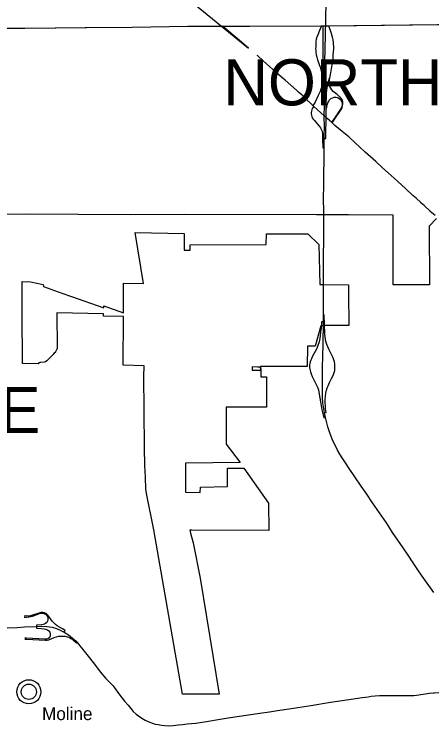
# Model space of a CAD drawing. Extents: x 0 to 851, y 0 to 440.
# Drawn here: x 378.43 to 401.2, y 321.16 to 359.94 of the extents above; entities that cross this region are included whole.
import ezdxf

# ---------------------------------------------------------------- set-up
doc = ezdxf.new("R2010")
doc.units = 0
for name, color, linetype in [('DV_X_Corp_Line', 7, 'Continuous'), ('GM_X_Corporation_Text', 7, 'Continuous'), ('GM_X_County', 7, 'Continuous'), ('GM_X_Interchange_Ramps', 7, 'Continuous'), ('GM_X_Interstate_Route', 7, 'Continuous'), ('GM_X_State_Route', 7, 'Continuous')]:
    doc.layers.add(name, color=color, linetype=linetype)

msp = doc.modelspace()

# ---------------------------------------------------------------- linework, layer by layer
at = {"layer": 'DV_X_Corp_Line'}
for points in [[(375.703, 359.197), (379.013, 359.176), (382.394, 359.212), (384.851, 359.238), (387.892, 359.281), (395.425, 359.31), (415.195, 359.534)], [(401.447, 348.807), (401.054, 348.391), (401.067, 345.188), (399.088, 345.195), (399.098, 348.986), (396.648, 348.999), (395.34, 349.005), (395.283, 349.006), (394.915, 349.002), (387.707, 349.029), (384.758, 349.005), (379.084, 349.033), (371.878, 349.031)]]:
    msp.add_lwpolyline(points, dxfattribs=at)
msp.add_lwpolyline([(378.861, 345.366), (379.32, 345.347), (380.003, 345.213), (380.023, 345.103), (381.02, 344.739), (381.547, 344.553), (383.317, 343.928), (383.315, 344.038), (384.385, 343.656), (384.388, 345.287), (385.483, 345.27), (385.027, 348.044), (387.697, 347.989), (387.7, 347.08), (388.025, 347.075), (388.019, 347.378), (392.169, 347.392), (392.176, 347.969), (394.444, 347.976), (395.035, 347.394), (395.093, 345.205), (395.254, 345.204), (395.31, 345.206), (396.661, 345.192), (396.663, 344.724), (396.666, 342.974), (395.363, 342.964), (395.311, 342.962), (395.215, 342.961), (395.183, 342.96), (395.146, 342.961), (394.841, 341.848), (394.425, 341.853), (394.405, 340.747), (393.308, 340.74), (392.197, 340.734), (391.866, 340.733), (391.867, 340.558), (391.862, 340.703), (391.69, 340.708), (391.398, 340.713), (391.398, 340.545), (391.867, 340.545), (391.868, 340.171), (392.181, 340.175), (392.187, 338.518), (389.994, 338.522), (389.994, 336.511), (390.742, 335.506), (387.76, 335.47), (387.764, 334.173), (387.767, 333.893), (388.571, 333.865), (388.58, 334.156), (390.063, 334.194), (390.062, 335.19), (390.947, 335.19), (392.297, 333.286), (392.311, 331.803), (388.108, 331.817), (387.997, 331.817), (388.037, 331.651), (388.184, 331.125), (388.559, 329.206), (389.6, 322.879), (387.61, 322.882), (386.05, 331.842), (385.642, 333.819), (385.6, 334.076), (385.581, 334.683), (385.56, 335.051), (385.556, 335.303), (385.54, 336.337), (385.501, 340.268), (385.51, 340.688), (385.516, 340.782), (384.37, 340.809), (384.384, 343.461), (383.299, 343.474), (383.295, 343.611), (380.759, 343.654), (380.772, 341.731), (380.778, 341.705), (380.76, 341.676), (380.719, 341.606), (380.68, 341.536), (380.671, 341.52), (380.614, 341.463), (380.594, 341.443), (380.546, 341.395), (380.45, 341.282), (380.39, 341.225), (380.313, 341.148), (380.204, 341.048), (380.141, 340.988), (380.064, 340.97), (379.877, 340.962), (379.823, 340.951), (379.776, 340.93), (379.743, 340.892), (378.884, 340.898), (378.868, 343.682), (378.866, 344.063)], close=True, dxfattribs=at)
for radius in [0.658, 0.417]:
    msp.add_circle((379.225, 323.008), radius, dxfattribs=at)
at = {"layer": 'GM_X_County'}
msp.add_lwpolyline([(377.893, 359.183), (379.009, 359.176), (382.288, 359.211), (384.851, 359.238), (387.892, 359.281), (388.261, 359.282), (388.38, 359.283), (388.712, 359.284), (388.751, 359.284), (389.413, 359.287), (389.783, 359.288), (390.584, 359.291), (391.285, 359.283), (395.187, 359.309), (395.259, 359.31), (395.406, 359.31), (395.583, 359.312), (400.152, 359.363), (403.796, 359.403)], dxfattribs=at)
at = {"layer": 'GM_X_Interchange_Ramps'}
for points in [[(395.259, 359.31), (395.25, 358.08), (395.238, 356.341), (395.232, 356.272), (395.22, 356.18), (395.201, 356.059), (395.179, 355.952), (395.155, 355.851), (395.104, 355.73), (395.011, 355.502), (394.846, 355.152), (394.768, 355.03), (394.705, 354.959)], [(395.187, 359.309), (395.138, 359.178), (395.078, 359.044), (394.985, 358.819), (394.931, 358.692), (394.897, 358.576), (394.879, 358.463), (394.879, 358.377), (394.881, 358.193), (394.876, 358.155)], [(395.846, 357.964), (395.851, 357.989), (395.849, 358.176), (395.842, 358.307), (395.833, 358.42), (395.815, 358.542), (395.782, 358.683), (395.721, 358.895), (395.583, 359.312)], [(394.876, 358.155), (394.863, 358.062), (394.866, 357.963), (394.876, 357.868), (394.902, 357.733), (394.929, 357.602), (394.969, 357.453), (395.104, 357.051), (395.148, 356.909), (395.18, 356.763), (395.203, 356.623), (395.215, 356.481), (395.22, 356.341), (395.238, 356.341)], [(395.758, 354.026), (395.845, 354.125), (396.259, 354.74), (396.309, 354.843), (396.337, 354.937), (396.351, 355.053), (396.345, 355.154), (396.32, 355.247), (396.274, 355.325), (396.219, 355.406), (396.035, 355.558), (395.816, 355.732), (395.749, 355.811), (395.692, 355.901), (395.643, 355.994), (395.627, 356.069), (395.608, 356.161), (395.609, 356.227), (395.618, 356.345), (395.634, 356.452), (395.638, 356.479), (395.691, 356.748), (395.783, 357.297), (395.813, 357.504), (395.828, 357.686), (395.838, 357.926), (395.846, 357.964)], [(395.326, 353.171), (395.415, 353.171), (395.419, 353.368), (395.437, 354.311), (395.447, 354.843), (395.46, 355.642), (395.472, 355.781), (395.496, 355.923), (395.529, 356.101), (395.614, 356.455), (395.634, 356.452)], [(395.447, 354.843), (395.475, 354.84), (395.481, 354.901), (395.501, 355.008), (395.533, 355.108), (395.579, 355.194), (395.628, 355.267), (395.695, 355.337), (395.779, 355.382), (395.881, 355.413), (395.979, 355.414), (396.076, 355.391), (396.144, 355.345), (396.211, 355.287), (396.263, 355.215), (396.308, 355.11), (396.309, 355.018), (396.289, 354.914), (396.257, 354.814), (395.819, 354.155), (395.728, 354.052)], [(394.762, 354.908), (394.726, 354.867), (394.684, 354.808), (394.648, 354.734), (394.633, 354.654), (394.624, 354.586), (394.623, 354.517), (394.632, 354.431), (394.652, 354.357), (394.682, 354.285), (394.723, 354.226), (394.776, 354.157), (395.066, 353.826), (395.125, 353.749), (395.166, 353.677), (395.195, 353.603), (395.219, 353.523), (395.233, 353.419), (395.239, 353.321), (395.239, 353.269), (395.241, 353.139), (395.259, 352.661), (395.331, 352.662)], [(395.918, 340.71), (395.919, 340.773), (395.906, 340.88), (395.888, 340.996), (395.86, 341.107), (395.818, 341.218), (395.769, 341.314), (395.575, 341.69), (395.521, 341.81), (395.476, 341.939), (395.429, 342.095), (395.396, 342.232), (395.38, 342.357), (395.369, 342.515), (395.334, 343.548), (395.29, 343.548)], [(395.288, 343.17), (395.186, 343.171), (395.164, 342.841), (395.138, 342.603), (395.111, 342.425), (395.09, 342.268), (395.05, 342.076), (394.984, 341.887), (394.924, 341.721), (394.682, 341.259), (394.63, 341.165), (394.595, 341.083), (394.567, 340.991), (394.544, 340.896), (394.535, 340.826), (394.534, 340.786), (394.534, 340.722)], [(394.534, 340.722), (394.533, 340.682), (394.544, 340.596), (394.576, 340.452), (394.615, 340.335), (394.672, 340.2), (394.915, 339.722), (394.978, 339.578), (395.017, 339.459), (395.047, 339.333), (395.132, 338.814), (395.203, 338.384), (395.304, 337.936), (395.402, 337.959)], [(395.352, 338.21), (395.441, 338.224), (395.409, 338.427), (395.395, 338.591), (395.39, 338.779), (395.39, 338.96), (395.4, 339.132), (395.424, 339.289), (395.46, 339.449), (395.495, 339.571), (395.54, 339.692), (395.62, 339.863), (395.732, 340.08), (395.797, 340.21), (395.838, 340.298), (395.879, 340.41), (395.902, 340.523), (395.912, 340.597), (395.918, 340.654), (395.918, 340.71)], [(381.158, 326.254), (381.213, 326.345), (381.063, 326.436), (380.902, 326.526), (380.778, 326.607), (380.68, 326.681), (380.584, 326.764), (380.505, 326.857), (380.4, 326.987), (380.317, 327.111), (380.245, 327.198), (380.163, 327.268), (380.084, 327.316), (379.982, 327.339), (379.884, 327.326), (379.765, 327.288), (379.365, 327.161), (379.265, 327.139), (379.188, 327.135), (379.093, 327.141), (378.974, 327.14)], [(378.975, 327.082), (379.096, 327.084), (379.217, 327.087), (379.334, 327.106), (379.426, 327.132), (379.539, 327.172), (379.715, 327.239), (379.867, 327.289), (379.958, 327.299), (380.015, 327.292), (380.085, 327.265), (380.139, 327.234), (380.191, 327.188), (380.233, 327.137), (380.259, 327.072), (380.266, 327.004), (380.263, 326.936), (380.244, 326.862), (380.202, 326.795), (380.14, 326.735), (380.079, 326.698), (380.013, 326.676), (379.911, 326.663), (379.639, 326.639), (379.642, 326.568)], [(379.642, 326.568), (379.647, 326.47), (379.904, 326.468), (380.057, 326.447), (380.154, 326.421), (380.241, 326.383), (380.318, 326.33), (380.367, 326.258), (380.392, 326.177), (380.394, 326.107), (380.382, 326.031), (380.356, 325.98), (380.318, 325.929), (380.256, 325.895), (380.193, 325.878), (380.093, 325.871), (379.1, 325.935), (378.998, 325.932)], [(378.999, 325.883), (379.102, 325.886), (380.142, 325.827), (380.229, 325.831), (380.314, 325.85), (380.611, 325.965), (380.742, 326.012), (380.868, 326.037), (380.974, 326.048), (381.086, 326.05), (381.207, 326.033), (381.318, 326.007), (381.4, 325.98), (381.517, 325.92), (381.589, 325.874), (381.668, 325.814), (381.829, 325.659), (381.865, 325.689)]]:
    msp.add_lwpolyline(points, dxfattribs=at)
at = {"layer": 'GM_X_Interstate_Route'}
for points in [[(395.335, 354.401), (395.344, 354.938), (395.35, 355.451), (395.356, 355.984), (395.369, 356.541), (395.373, 357.349), (395.385, 358.052), (395.386, 358.087), (395.395, 358.764), (395.601, 368.879)], [(395.313, 351.273), (395.314, 351.293), (395.325, 351.932), (395.331, 352.662), (395.326, 353.171), (395.326, 353.304), (395.341, 353.78), (395.335, 354.401)], [(395.306, 349.017), (395.306, 349.018), (395.307, 349.176), (395.299, 349.914), (395.308, 350.604), (395.311, 351.161), (395.313, 351.273)], [(395.305, 348.843), (395.306, 349.017)], [(395.292, 345.198), (395.292, 345.292), (395.294, 345.798), (395.297, 346.358), (395.3, 346.925), (395.306, 347.458), (395.304, 348.052), (395.304, 348.649), (395.305, 348.842), (395.305, 348.843)], [(395.293, 345.111), (395.292, 345.178), (395.292, 345.198)], [(395.288, 342.995), (395.288, 343.17), (395.29, 343.548), (395.294, 344.285), (395.294, 344.845), (395.293, 345.09), (395.293, 345.111)], [(395.282, 342.469), (395.286, 342.672), (395.287, 342.898), (395.287, 342.907)], [(395.287, 342.907), (395.287, 342.985), (395.288, 342.995)], [(401.304, 328.412), (401.029, 328.806), (400.771, 329.187), (400.517, 329.547), (400.19, 330.036), (399.903, 330.453), (399.635, 330.847), (399.351, 331.275), (399.064, 331.696), (399.001, 331.777), (398.722, 332.209), (398.34, 332.762), (397.964, 333.312), (397.647, 333.774), (397.341, 334.219), (397.004, 334.718), (396.688, 335.183), (396.492, 335.482), (396.31, 335.767), (396.186, 335.964), (396.059, 336.181), (395.939, 336.418), (395.826, 336.644), (395.711, 336.925), (395.621, 337.181), (395.532, 337.445), (395.454, 337.741), (395.402, 337.959), (395.373, 338.081), (395.352, 338.21), (395.264, 338.751), (395.235, 339.033), (395.237, 339.318), (395.24, 339.667), (395.236, 340.197), (395.237, 340.677), (395.238, 340.716), (395.254, 341.264), (395.274, 341.971), (395.282, 342.462), (395.282, 342.469)]]:
    msp.add_lwpolyline(points, dxfattribs=at)
at = {"layer": 'GM_X_State_Route'}
for points in [[(385.51, 362.737), (391.198, 358.088), (390.844, 358.402), (390.819, 358.423)], [(390.819, 358.423), (389.783, 359.288)], [(393.938, 355.697), (393.902, 355.73), (393.828, 355.797), (393.518, 356.075), (393.2, 356.342), (393.118, 356.421), (392.881, 356.622), (392.732, 356.752), (392.505, 356.945), (392.177, 357.232), (392.006, 357.395), (391.711, 357.668), (391.678, 357.695)], [(394.261, 355.393), (394.134, 355.524), (393.938, 355.697)], [(395.492, 354.262), (395.464, 354.286), (395.437, 354.311), (395.335, 354.401), (394.762, 354.908), (394.705, 354.959), (394.28, 355.374), (394.261, 355.393)], [(396.746, 353.187), (396.682, 353.248), (396.319, 353.554), (395.919, 353.881), (395.758, 354.026), (395.728, 354.052), (395.492, 354.262)], [(397.851, 352.171), (397.573, 352.425), (397.252, 352.716), (397.022, 352.927), (396.938, 353.002), (396.746, 353.187)], [(400.593, 349.673), (400.35, 349.904), (400.162, 350.06), (399.77, 350.433), (399.34, 350.824), (399.155, 350.999), (398.826, 351.289), (398.517, 351.57), (398.152, 351.903), (397.864, 352.159), (397.851, 352.171)], [(401.112, 349.195), (400.788, 349.515), (400.604, 349.661), (400.593, 349.673)], [(401.379, 348.963), (401.118, 349.19), (401.112, 349.195)], [(376.663, 326.416), (376.669, 326.417), (376.79, 326.423), (377.452, 326.463), (378.051, 326.488), (378.603, 326.521), (378.981, 326.542)], [(378.981, 326.542), (379.642, 326.568), (379.9, 326.579), (380.204, 326.568), (380.493, 326.523), (380.732, 326.46), (380.927, 326.375), (381.158, 326.254), (381.388, 326.111), (381.608, 325.941), (381.8, 325.768), (381.865, 325.689), (382.234, 325.226), (382.525, 324.853), (382.852, 324.438), (383.12, 324.092), (383.428, 323.725), (383.816, 323.333), (384.081, 322.967), (384.447, 322.505), (384.642, 322.278), (384.793, 322.094), (384.917, 321.944), (385.076, 321.797), (385.211, 321.694), (385.39, 321.57), (385.572, 321.466), (385.761, 321.372), (385.967, 321.291), (386.111, 321.251), (386.276, 321.219), (386.462, 321.187), (386.633, 321.166), (386.823, 321.158), (387.095, 321.175), (387.378, 321.202), (387.598, 321.234), (387.856, 321.264), (388.338, 321.307), (388.912, 321.394), (389.55, 321.497), (390.097, 321.582), (391.208, 321.747), (391.816, 321.84), (392.35, 321.919), (392.792, 321.988), (393.42, 322.084), (394.602, 322.265), (395.683, 322.437), (396.19, 322.512), (396.676, 322.584), (396.802, 322.603), (397.401, 322.696), (397.73, 322.743), (397.891, 322.774), (398.106, 322.797), (398.354, 322.805)], [(398.354, 322.805), (398.357, 322.805), (398.588, 322.812), (398.95, 322.809), (399.482, 322.807), (399.934, 322.812), (400.226, 322.814), (400.373, 322.825), (400.732, 322.876), (401.075, 322.927), (401.295, 322.946), (401.347, 322.95), (401.819, 322.984), (402.324, 322.992), (402.541, 322.994), (402.696, 322.996)]]:
    msp.add_lwpolyline(points, dxfattribs=at)

# ---------------------------------------------------------------- texts
at = {"layer": 'DV_X_Corp_Line'}
msp.add_text('Moline', height=0.6979, rotation=0, dxfattribs=at).set_placement((379.946, 321.468))
at = {"layer": 'GM_X_Corporation_Text'}
for s, p in [('NORTHWOOD', (389.835, 354.969)), ('WALBRIDGE', (359.697, 337.105))]:
    msp.add_text(s, height=2.5126, rotation=0, dxfattribs=at).set_placement(p)

doc.saveas('drawing.dxf')
